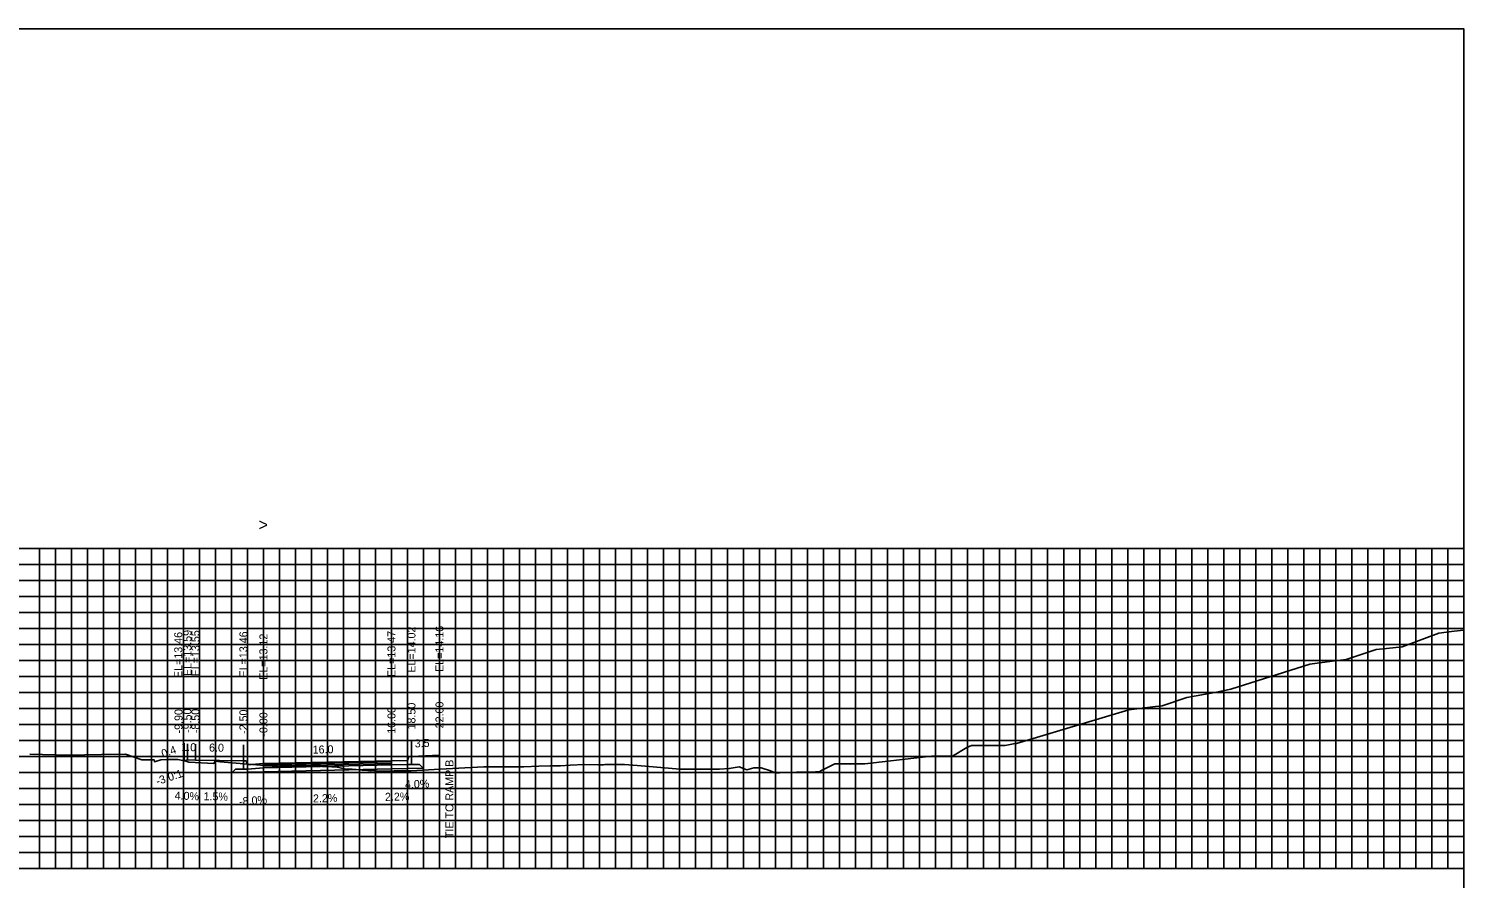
# Model space of a CAD drawing. Extents: x 1797645 to 1803805, y 248417 to 250269.
# Drawn here: x 1803281.7 to 1803461.1, y 250163.2 to 250269.4 of the extents above; entities that cross this region are included whole.
import ezdxf

# ---------------------------------------------------------------- set-up
doc = ezdxf.new("R2010")
doc.units = 0
for name, color, linetype in [('3', 7, 'Continuous'), ('4', 7, 'Continuous'), ('60', 7, 'Continuous'), ('BASE', 7, 'Continuous'), ('CL-CNST', 7, 'Continuous'), ('Level 62', 7, 'Continuous'), ('LOWER BINDER', 7, 'Continuous'), ('M-ROADS', 7, 'Continuous'), ('UPPER BINDER', 7, 'Continuous'), ('WEARING', 7, 'Continuous')]:
    doc.layers.add(name, color=color, linetype=linetype)

msp = doc.modelspace()

# ---------------------------------------------------------------- linework, layer by layer
for p, q in [((1803301.1, 250177.89), (1803301.1, 250179.89)), ((1803301.5, 250178.02), (1803301.5, 250180.02)), ((1803302.5, 250177.98), (1803302.5, 250179.98)), ((1803308.5, 250177.89), (1803308.5, 250179.89)), ((1803308.5, 250177.89), (1803308.5, 250179.89)), ((1803311, 250177.55), (1803311, 250179.55)), ((1803327, 250177.91), (1803327, 250179.91)), ((1803329.5, 250178.45), (1803329.5, 250180.45)), ((1803333, 250178.59), (1803333, 250180.59))]:
    msp.add_line(p, q)
for points in [[(1803161, 250079.43), (1803461, 250079.43), (1803461, 250269.43), (1803161, 250269.43)], [(1803311, 250177.55), (1803309, 250177.39), (1803308.83, 250177.89), (1803308.5, 250177.89), (1803308.5, 250176.86), (1803309, 250176.86), (1803311, 250177.02)], [(1803327, 250177.91), (1803329, 250177.95), (1803329.17, 250178.45), (1803329.5, 250178.45), (1803329.5, 250177.42), (1803329, 250177.42), (1803327, 250177.38)]]:
    msp.add_lwpolyline(points, close=True)
at = {"layer": '3'}
msp.add_line((1803333, 250178.59), (1803333, 250171.8), dxfattribs=at)
at = {"layer": '60'}
for p, q in [((1803461, 250164.43), (1803461, 250204.43)), ((1803461.06, 250204.43), (1803461, 250204.43)), ((1803461.06, 250194.43), (1803461, 250194.43)), ((1803461.06, 250184.43), (1803461, 250184.43)), ((1803461.06, 250174.43), (1803461, 250174.43)), ((1803161, 250164.43), (1803461, 250164.43)), ((1803291, 250164.37), (1803291, 250164.43)), ((1803301, 250164.37), (1803301, 250164.43)), ((1803311, 250164.37), (1803311, 250164.43)), ((1803321, 250164.37), (1803321, 250164.43)), ((1803331, 250164.37), (1803331, 250164.43)), ((1803341, 250164.37), (1803341, 250164.43)), ((1803351, 250164.37), (1803351, 250164.43)), ((1803361, 250164.37), (1803361, 250164.43)), ((1803371, 250164.37), (1803371, 250164.43)), ((1803381, 250164.37), (1803381, 250164.43)), ((1803391, 250164.37), (1803391, 250164.43)), ((1803401, 250164.37), (1803401, 250164.43)), ((1803411, 250164.37), (1803411, 250164.43)), ((1803421, 250164.37), (1803421, 250164.43)), ((1803431, 250164.37), (1803431, 250164.43)), ((1803441, 250164.37), (1803441, 250164.43)), ((1803451, 250164.37), (1803451, 250164.43)), ((1803461, 250164.37), (1803461, 250164.43)), ((1803461.06, 250164.43), (1803461, 250164.43))]:
    msp.add_line(p, q, dxfattribs=at)
at = {"layer": 'BASE'}
msp.add_lwpolyline([(1803311, 250177.02), (1803327, 250177.38), (1803329, 250177.42), (1803329.5, 250177.42), (1803330.5, 250177.44), (1803330.98, 250176.96), (1803327, 250176.88), (1803311, 250176.52), (1803307.09, 250176.44), (1803307.5, 250176.84), (1803308.5, 250176.86), (1803309, 250176.86)], close=True, dxfattribs=at)
at = {"layer": 'CL-CNST'}
msp.add_lwpolyline([(1803301.1, 250177.89), (1803301.5, 250178.02), (1803302.5, 250177.98), (1803308.5, 250177.89), (1803308.5, 250177.89), (1803308.83, 250177.89), (1803309, 250177.39), (1803311, 250177.55), (1803327, 250177.91), (1803329, 250177.95), (1803329.17, 250178.45), (1803329.5, 250178.45), (1803333, 250178.59)], dxfattribs=at)
at = {"layer": 'Level 62'}
for p, q in [((1803161, 250204.43), (1803461, 250204.43)), ((1803283, 250164.43), (1803283, 250204.43)), ((1803285, 250164.43), (1803285, 250204.43)), ((1803287, 250164.43), (1803287, 250204.43)), ((1803289, 250164.43), (1803289, 250204.43)), ((1803291, 250164.43), (1803291, 250204.43)), ((1803293, 250164.43), (1803293, 250204.43)), ((1803295, 250164.43), (1803295, 250204.43)), ((1803297, 250164.43), (1803297, 250204.43)), ((1803299, 250164.43), (1803299, 250204.43)), ((1803301, 250164.43), (1803301, 250204.43)), ((1803303, 250164.43), (1803303, 250204.43)), ((1803305, 250164.43), (1803305, 250204.43)), ((1803307, 250164.43), (1803307, 250204.43)), ((1803309, 250164.43), (1803309, 250204.43)), ((1803311, 250164.43), (1803311, 250204.43)), ((1803313, 250164.43), (1803313, 250204.43)), ((1803315, 250164.43), (1803315, 250204.43)), ((1803317, 250164.43), (1803317, 250204.43)), ((1803319, 250164.43), (1803319, 250204.43)), ((1803321, 250164.43), (1803321, 250204.43)), ((1803323, 250164.43), (1803323, 250204.43)), ((1803325, 250164.43), (1803325, 250204.43)), ((1803327, 250164.43), (1803327, 250204.43)), ((1803329, 250164.43), (1803329, 250204.43)), ((1803331, 250164.43), (1803331, 250204.43)), ((1803333, 250164.43), (1803333, 250204.43)), ((1803335, 250164.43), (1803335, 250204.43)), ((1803337, 250164.43), (1803337, 250204.43)), ((1803339, 250164.43), (1803339, 250204.43)), ((1803341, 250164.43), (1803341, 250204.43)), ((1803343, 250164.43), (1803343, 250204.43)), ((1803345, 250164.43), (1803345, 250204.43)), ((1803347, 250164.43), (1803347, 250204.43)), ((1803349, 250164.43), (1803349, 250204.43)), ((1803351, 250164.43), (1803351, 250204.43)), ((1803353, 250164.43), (1803353, 250204.43)), ((1803355, 250164.43), (1803355, 250204.43)), ((1803357, 250164.43), (1803357, 250204.43)), ((1803359, 250164.43), (1803359, 250204.43)), ((1803361, 250164.43), (1803361, 250204.43)), ((1803363, 250164.43), (1803363, 250204.43)), ((1803365, 250164.43), (1803365, 250204.43)), ((1803367, 250164.43), (1803367, 250204.43)), ((1803369, 250164.43), (1803369, 250204.43)), ((1803371, 250164.43), (1803371, 250204.43)), ((1803373, 250164.43), (1803373, 250204.43)), ((1803375, 250164.43), (1803375, 250204.43)), ((1803377, 250164.43), (1803377, 250204.43)), ((1803379, 250164.43), (1803379, 250204.43)), ((1803381, 250164.43), (1803381, 250204.43)), ((1803383, 250164.43), (1803383, 250204.43)), ((1803385, 250164.43), (1803385, 250204.43)), ((1803387, 250164.43), (1803387, 250204.43)), ((1803389, 250164.43), (1803389, 250204.43)), ((1803391, 250164.43), (1803391, 250204.43)), ((1803393, 250164.43), (1803393, 250204.43)), ((1803395, 250164.43), (1803395, 250204.43)), ((1803397, 250164.43), (1803397, 250204.43)), ((1803399, 250164.43), (1803399, 250204.43)), ((1803401, 250164.43), (1803401, 250204.43)), ((1803403, 250164.43), (1803403, 250204.43)), ((1803405, 250164.43), (1803405, 250204.43)), ((1803407, 250164.43), (1803407, 250204.43)), ((1803409, 250164.43), (1803409, 250204.43)), ((1803411, 250164.43), (1803411, 250204.43)), ((1803413, 250164.43), (1803413, 250204.43)), ((1803415, 250164.43), (1803415, 250204.43)), ((1803417, 250164.43), (1803417, 250204.43)), ((1803419, 250164.43), (1803419, 250204.43)), ((1803421, 250164.43), (1803421, 250204.43)), ((1803423, 250164.43), (1803423, 250204.43)), ((1803425, 250164.43), (1803425, 250204.43)), ((1803427, 250164.43), (1803427, 250204.43)), ((1803429, 250164.43), (1803429, 250204.43)), ((1803431, 250164.43), (1803431, 250204.43)), ((1803433, 250164.43), (1803433, 250204.43)), ((1803435, 250164.43), (1803435, 250204.43)), ((1803437, 250164.43), (1803437, 250204.43)), ((1803439, 250164.43), (1803439, 250204.43)), ((1803441, 250164.43), (1803441, 250204.43)), ((1803443, 250164.43), (1803443, 250204.43)), ((1803445, 250164.43), (1803445, 250204.43)), ((1803447, 250164.43), (1803447, 250204.43)), ((1803449, 250164.43), (1803449, 250204.43)), ((1803451, 250164.43), (1803451, 250204.43)), ((1803453, 250164.43), (1803453, 250204.43)), ((1803455, 250164.43), (1803455, 250204.43)), ((1803457, 250164.43), (1803457, 250204.43)), ((1803459, 250164.43), (1803459, 250204.43)), ((1803461, 250164.43), (1803461, 250204.43)), ((1803161, 250202.43), (1803461, 250202.43)), ((1803161, 250200.43), (1803461, 250200.43)), ((1803161, 250198.43), (1803461, 250198.43)), ((1803161, 250196.43), (1803461, 250196.43)), ((1803161, 250194.43), (1803461, 250194.43)), ((1803161, 250192.43), (1803461, 250192.43)), ((1803161, 250190.43), (1803461, 250190.43)), ((1803161, 250188.43), (1803461, 250188.43)), ((1803161, 250186.43), (1803461, 250186.43)), ((1803161, 250184.43), (1803461, 250184.43)), ((1803161, 250182.43), (1803461, 250182.43)), ((1803161, 250180.43), (1803461, 250180.43)), ((1803161, 250178.43), (1803461, 250178.43)), ((1803161, 250176.43), (1803461, 250176.43)), ((1803161, 250174.43), (1803461, 250174.43)), ((1803161, 250172.43), (1803461, 250172.43)), ((1803161, 250170.43), (1803461, 250170.43)), ((1803161, 250168.43), (1803461, 250168.43)), ((1803161, 250166.43), (1803461, 250166.43)), ((1803161, 250164.43), (1803461, 250164.43))]:
    msp.add_line(p, q, dxfattribs=at)
at = {"layer": 'LOWER BINDER'}
msp.add_lwpolyline([(1803327, 250177.38), (1803327, 250177.38), (1803327, 250177.57), (1803311, 250177.21), (1803311, 250177.02)], close=True, dxfattribs=at)
at = {"layer": 'M-ROADS'}
msp.add_lwpolyline([(1803281.79, 250178.72), (1803286.61, 250178.59), (1803290.78, 250178.68), (1803293.75, 250178.72), (1803295.79, 250178.04), (1803297.34, 250178.04), (1803297.37, 250177.78), (1803298.17, 250178.04), (1803299.07, 250178.05), (1803299.78, 250178.05), (1803300.06, 250178.05), (1803300.29, 250178.05), (1803301.31, 250177.85), (1803301.66, 250177.71), (1803304.82, 250177.57), (1803304.96, 250177.85), (1803305.59, 250177.76), (1803311.65, 250177.29), (1803311.81, 250177.26), (1803312.08, 250177.25), (1803312.15, 250177.24), (1803312.18, 250177.24), (1803312.22, 250177.24), (1803312.49, 250177.24), (1803318.28, 250177.18), (1803319.56, 250177.13), (1803319.97, 250177.15), (1803320.05, 250177.15), (1803321.13, 250176.91), (1803322.09, 250176.87), (1803323.13, 250176.78), (1803323.34, 250176.75), (1803323.7, 250176.72), (1803324.38, 250176.65), (1803324.48, 250176.67), (1803324.9, 250176.63), (1803326.56, 250176.61), (1803326.86, 250176.62), (1803327.35, 250176.63), (1803327.42, 250176.63), (1803327.63, 250176.63), (1803329.46, 250176.63), (1803333.03, 250176.84), (1803338.55, 250177.15), (1803340.4, 250177.16), (1803340.91, 250177.16), (1803340.97, 250177.16), (1803341.13, 250177.15), (1803342.35, 250177.15), (1803343.54, 250177.15), (1803345.41, 250177.21), (1803346.82, 250177.26), (1803347.42, 250177.26), (1803348.13, 250177.26), (1803349.33, 250177.35), (1803351.12, 250177.42), (1803352.86, 250177.41), (1803353.51, 250177.41), (1803353.67, 250177.43), (1803355.66, 250177.42), (1803356.11, 250177.42), (1803358.76, 250177.21), (1803363.02, 250176.86), (1803363.65, 250176.86), (1803365.46, 250176.85), (1803365.67, 250176.86), (1803365.67, 250176.86), (1803368.01, 250176.85), (1803369.2, 250176.93), (1803370.43, 250177.14), (1803371.4, 250176.79), (1803372.29, 250177.03), (1803373.19, 250177.03), (1803374.35, 250176.63), (1803375, 250176.41), (1803375.51, 250176.41), (1803377.61, 250176.47), (1803380, 250176.54), (1803380.23, 250176.54), (1803380.44, 250176.54), (1803380.75, 250176.7), (1803382.42, 250177.53), (1803383.49, 250177.53), (1803384.76, 250177.53), (1803385.47, 250177.52), (1803386.15, 250177.52), (1803393.36, 250178.36), (1803394.49, 250178.49), (1803394.67, 250178.48), (1803394.94, 250178.49), (1803397.11, 250178.5), (1803398.91, 250179.58), (1803399.49, 250179.82), (1803401.76, 250179.82), (1803403.7, 250179.82), (1803404.72, 250180.01), (1803405.1, 250180.07), (1803419.13, 250184.28), (1803422.48, 250184.68), (1803423.32, 250184.78), (1803426.41, 250185.8), (1803429.88, 250186.46), (1803431.87, 250186.84), (1803441.74, 250190), (1803444.54, 250190.35), (1803446.32, 250190.58), (1803450.03, 250191.8), (1803451.36, 250191.95), (1803453.29, 250192.16), (1803457.9, 250193.84), (1803459.79, 250194.09), (1803461, 250194.24)], dxfattribs=at)
at = {"layer": 'UPPER BINDER'}
msp.add_lwpolyline([(1803327, 250177.57), (1803327, 250177.76), (1803311, 250177.4), (1803311, 250177.21)], close=True, dxfattribs=at)
at = {"layer": 'WEARING'}
msp.add_lwpolyline([(1803327, 250177.76), (1803327, 250177.91), (1803311, 250177.55), (1803311, 250177.4)], close=True, dxfattribs=at)

# ---------------------------------------------------------------- texts
msp.add_text('-3.0:1', height=1, rotation=18.4349).set_placement((1803297.76, 250174.84))
at = {"layer": '3'}
for s, p in [('EL=13.46', (1803300.86, 250188.25)), ('EL=13.59', (1803302, 250188.5)), ('EL=13.55', (1803303, 250188.46)), ('EL=13.46', (1803309, 250188.32)), ('EL=13.46', (1803309, 250188.32)), ('EL=13.12', (1803311.5, 250188.03)), ('EL=13.47', (1803327.5, 250188.38)), ('EL=14.02', (1803330, 250188.92)), ('EL=14.16', (1803333.5, 250189.01)), ('18.50', (1803330, 250181.82)), ('22.00', (1803333.5, 250181.96)), ('-9.90', (1803300.89, 250181.32)), ('-9.50', (1803302, 250181.39)), ('-8.50', (1803303, 250181.35)), ('-2.50', (1803309, 250181.26)), ('-2.50', (1803309, 250181.26)), ('-0.00', (1803311.5, 250180.92)), ('16.00', (1803327.5, 250181.28)), ('TIE TO RAMP B', (1803334.74, 250168.24))]:
    msp.add_text(s, height=1, rotation=90, dxfattribs=at).set_placement(p)
at = {"layer": '4'}
for s, rotation, p in [('0.4', 18.4349, (1803298.44, 250178.29)), ('1.0', 357.7094, (1803300.72, 250179.16)), ('6.0', 359.1406, (1803304.2, 250179.06)), ('16.0', 1.2603, (1803317.16, 250178.79)), ('3.5', 2.2906, (1803329.92, 250179.57)), ('4.0%', 357.7094, (1803299.89, 250173.08)), ('1.5%', 359.1406, (1803303.51, 250172.97)), ('2.2%', 1.2603, (1803326.2, 250172.89)), ('4.0%', 2.2906, (1803328.7, 250174.44)), ('-8.0%', 4.5739, (1803308, 250172.3)), ('2.2%', 1.2603, (1803317.2, 250172.69))]:
    msp.add_text(s, height=1, rotation=rotation, dxfattribs=at).set_placement(p)
at = {"layer": '60'}
msp.add_text('>', height=1.5, dxfattribs=at).set_placement((1803310.39, 250206.68))

doc.saveas('drawing.dxf')
